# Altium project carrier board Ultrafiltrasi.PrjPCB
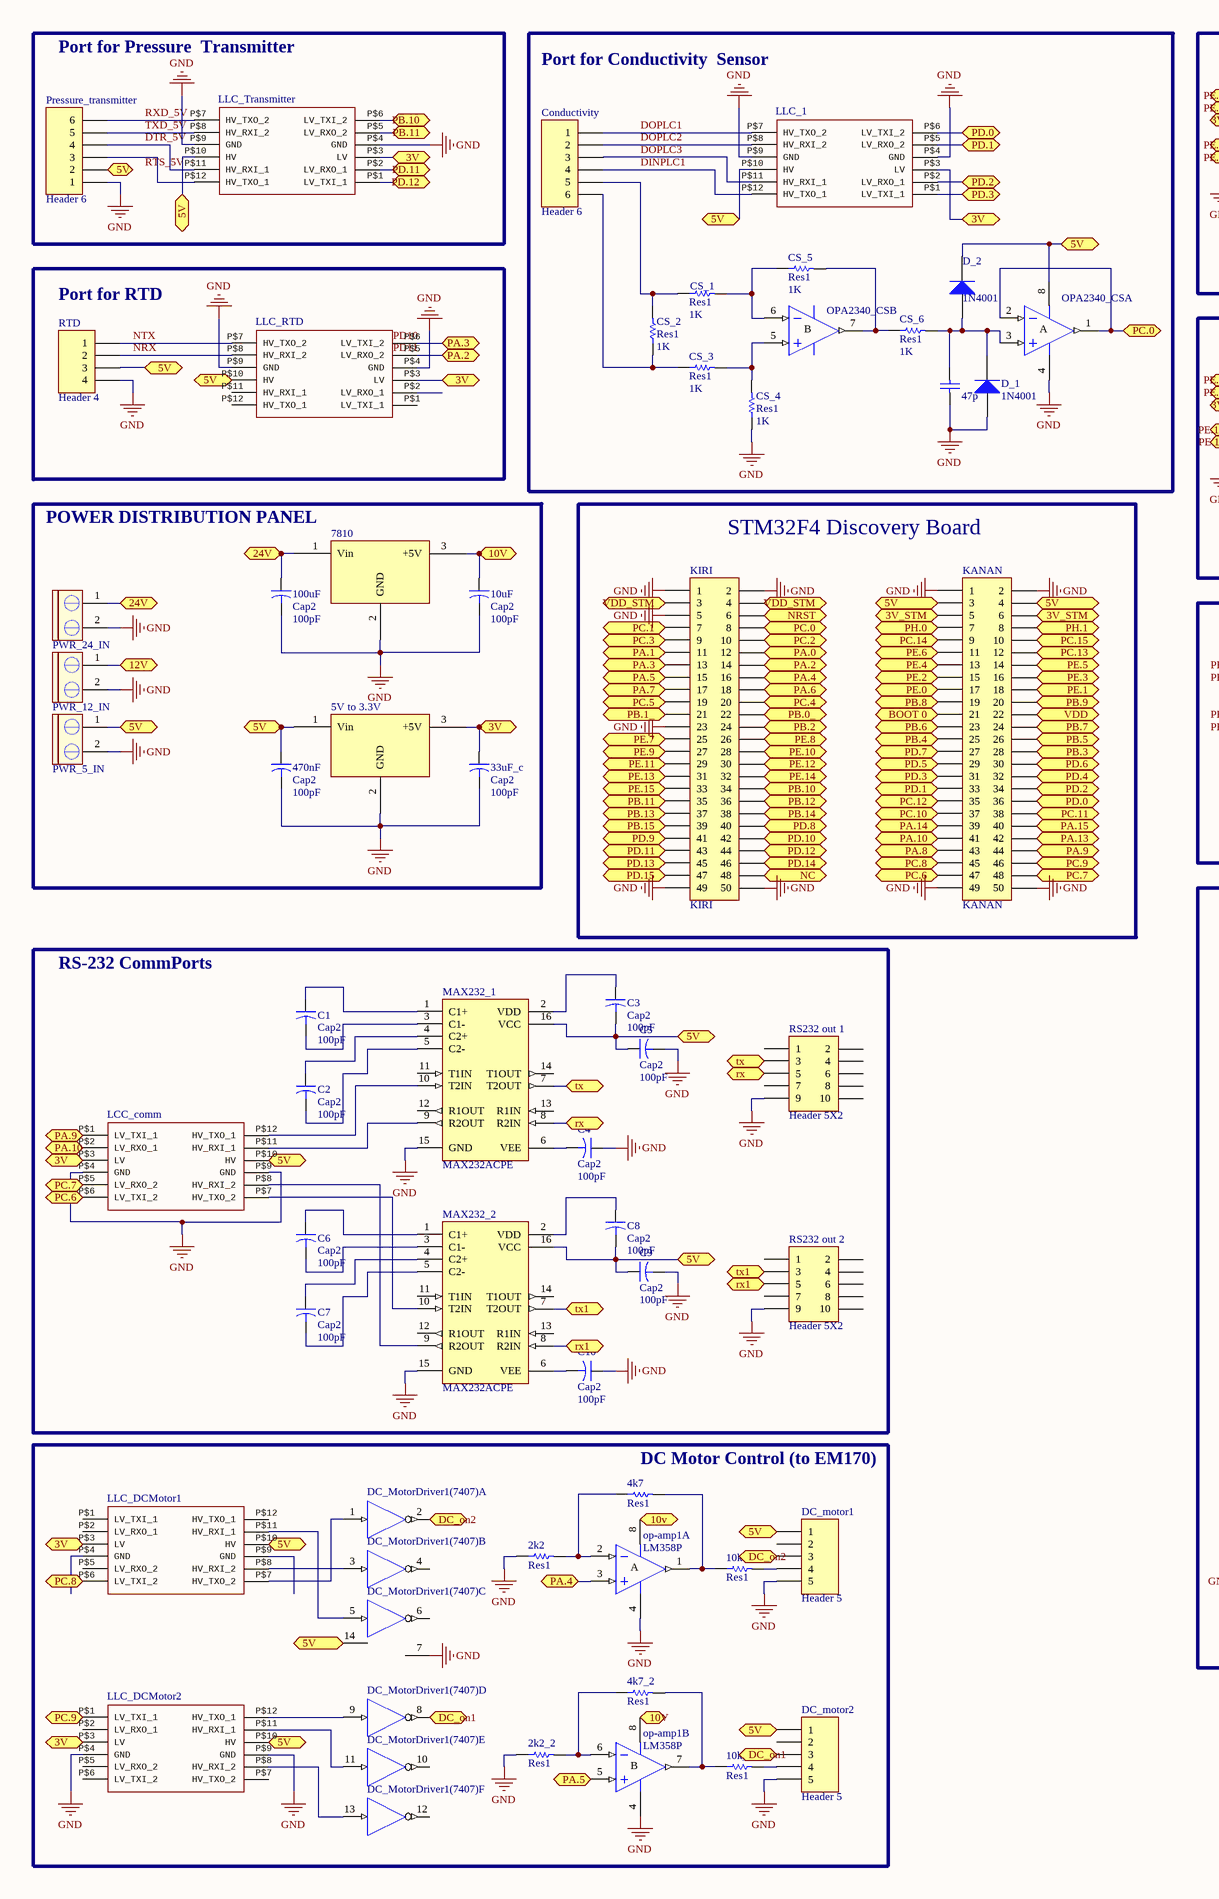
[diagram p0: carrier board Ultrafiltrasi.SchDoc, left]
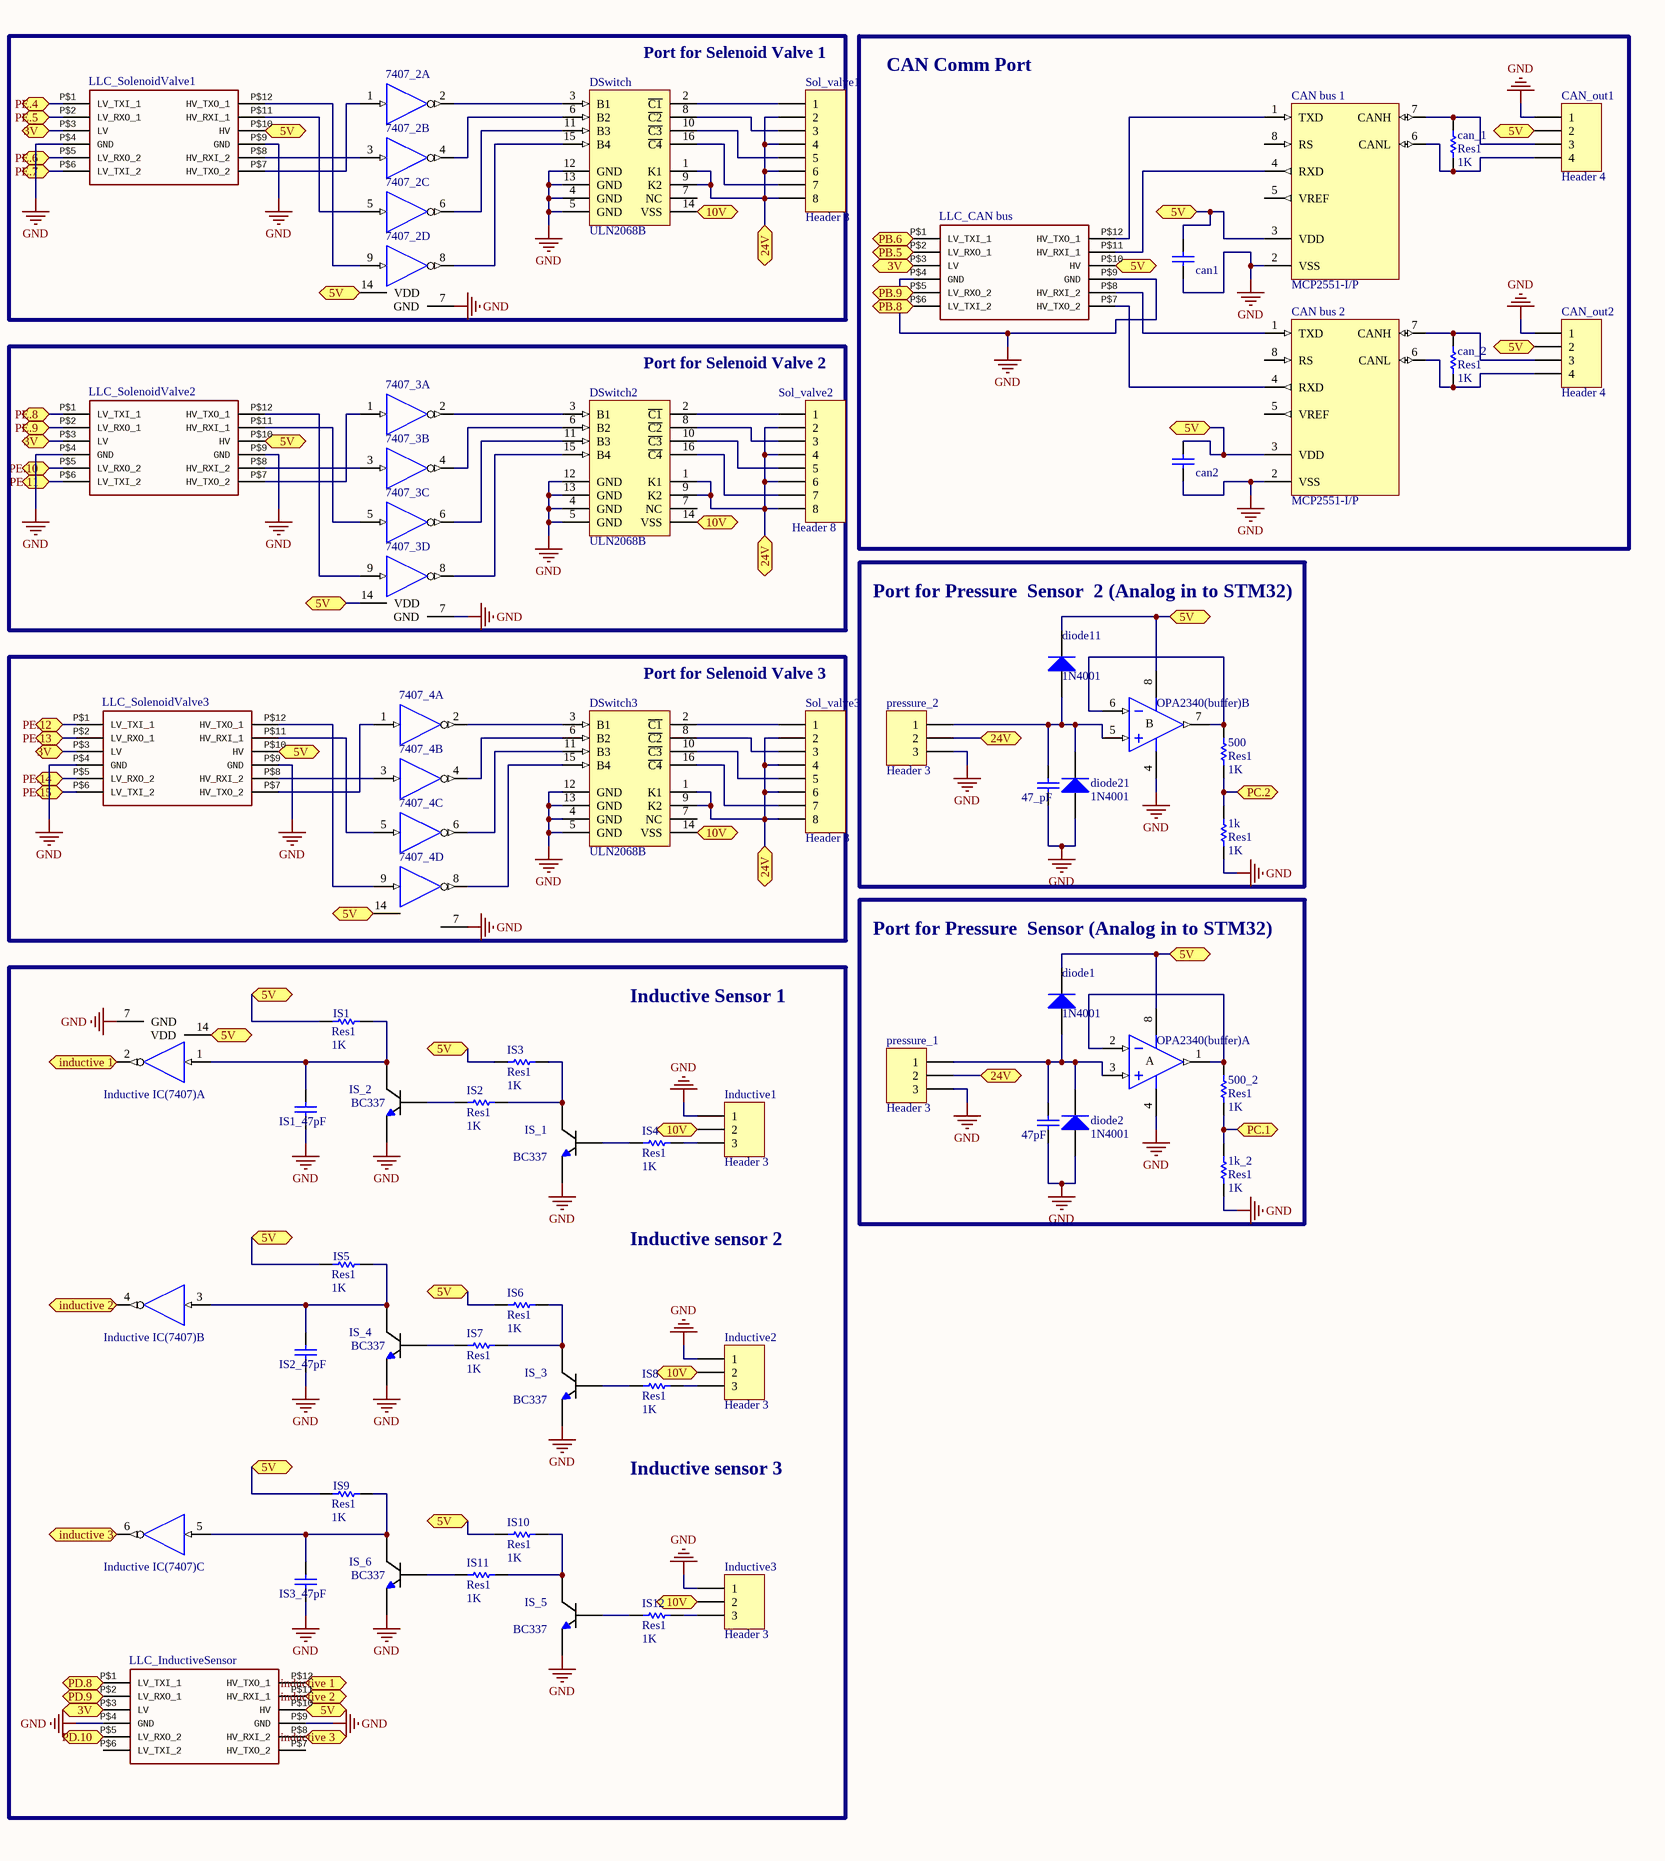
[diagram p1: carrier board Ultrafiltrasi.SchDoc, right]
1 sheet, 114 parts. Net scope: flat (ports and power ports of the same name join across sheets).
Board file: carrier board Ultrafiltrasi.PcbDoc

## Sheet carrier board Ultrafiltrasi.SchDoc: Carrier Board Ultrafiltrasi
size A2

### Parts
1k  Res1  value 1K  [AXIAL-0.3]
1k_2  Res1  value 1K  [AXIAL-0.3]
2k2  Res1  [AXIAL-0.3]
2k2_2  Res1  [AXIAL-0.3]
4k7  Res1  [AXIAL-0.3]
4k7_2  Res1  [AXIAL-0.3]
5V_to_3.3V  7805  [My_TO-220]  (value not drawn)
10k  Res1  [AXIAL-0.3]
10k_2  Res1  [AXIAL-0.3]
10uF  Cap2  value 100pF  [CAPR5-4X5]
33uF_c  Cap2  value 100pF  [CAPR5-4X5]
47_pF  Cap  [My_cap100n]  (value not drawn)
47p  Cap  [My_cap100n]  (value not drawn)
47pF  Cap  [My_cap100n]  (value not drawn)
100uF  Cap2  value 100pF  [CAPR5-4X5]
470nF  Cap2  value 100pF  [CAPR5-4X5]
500  Res1  value 1K  [AXIAL-0.3]
500_2  Res1  value 1K  [AXIAL-0.3]
7407_2  7407  [646-06]  (value not drawn)  (parts A,B,C,D of 6)
7407_3  7407  [646-06]  (value not drawn)  (parts A,B,C,D of 6)
7407_4  7407  [646-06]  (value not drawn)  (parts A,B,C,D of 6)
7810  7805  [My_TO-220]  (value not drawn)
C1  Cap2  value 100pF  [CAPR5-4X5]
C2  Cap2  value 100pF  [CAPR5-4X5]
C3  Cap2  value 100pF  [CAPR5-4X5]
C4  Cap2  value 100pF  [CAPR5-4X5]
C5  Cap2  value 100pF  [CAPR5-4X5]
C6  Cap2  value 100pF  [CAPR5-4X5]
C7  Cap2  value 100pF  [CAPR5-4X5]
C8  Cap2  value 100pF  [CAPR5-4X5]
C9  Cap2  value 100pF  [CAPR5-4X5]
C10  Cap2  value 100pF  [CAPR5-4X5]
can1  Cap  [My_cap100n]  (value not drawn)
can2  Cap  [My_cap100n]  (value not drawn)
can_1  Res1  value 1K  [AXIAL-0.3]
can_2  Res1  value 1K  [AXIAL-0.3]
CAN_bus_1  MCP2551-I/P  [PDIP300-P8]
CAN_bus_2  MCP2551-I/P  [PDIP300-P8]
CAN_out1  Header 4  [HDR1X4]
CAN_out2  Header 4  [HDR1X4]
Conductivity  Header 6  [HDR1X6]
CS_1  Res1  value 1K  [AXIAL-0.3]
CS_2  Res1  value 1K  [AXIAL-0.3]
CS_3  Res1  value 1K  [AXIAL-0.3]
CS_4  Res1  value 1K  [AXIAL-0.3]
CS_5  Res1  value 1K  [AXIAL-0.3]
CS_6  Res1  value 1K  [AXIAL-0.3]
D_1  1N4001  [DO-41]
D_2  1N4001  [DO-41]
DC_motor1  Header 5  [HDR1X5]
DC_motor2  Header 5  [HDR1X5]
DC_MotorDriver1(7407)  SN74LS14N  [646-06]  (value not drawn)  (parts A,B,C,D,E,F of 6)
diode1  1N4001  [DO-41]
diode2  1N4001  [DO-41]
diode11  1N4001  [DO-41]
diode21  1N4001  [DO-41]
DSwitch  ULN2068B  [648C-02]
DSwitch2  ULN2068B  [648C-02]
DSwitch3  ULN2068B  [648C-02]
Inductive1  Header 3  [HDR1X3]
Inductive2  Header 3  [HDR1X3]
Inductive3  Header 3  [HDR1X3]
Inductive_IC(7407)  SN74LS14N  [646-06]  (value not drawn)  (parts A,B,C of 6)
IS1  Res1  value 1K  [AXIAL-0.3]
IS1_47pF  Cap  [My_cap100n]  (value not drawn)
IS2  Res1  value 1K  [AXIAL-0.3]
IS2_47pF  Cap  [My_cap100n]  (value not drawn)
IS3  Res1  value 1K  [AXIAL-0.3]
IS3_47pF  Cap  [My_cap100n]  (value not drawn)
IS4  Res1  value 1K  [AXIAL-0.3]
IS5  Res1  value 1K  [AXIAL-0.3]
IS6  Res1  value 1K  [AXIAL-0.3]
IS7  Res1  value 1K  [AXIAL-0.3]
IS8  Res1  value 1K  [AXIAL-0.3]
IS9  Res1  value 1K  [AXIAL-0.3]
IS10  Res1  value 1K  [AXIAL-0.3]
IS11  Res1  value 1K  [AXIAL-0.3]
IS12  Res1  value 1K  [AXIAL-0.3]
IS_1  BC337  [E3]
IS_2  BC337  [TO-92]
IS_3  BC337  [TO-92]
IS_4  BC337  [transistor]
IS_5  BC337  [TO-92]
IS_6  BC337  [TO-92]
KANAN  KANAN  [HDR2X25]
KIRI  KIRI  [HDR2X25]
LCC_comm  Logic Level Converter (3.3v - 5v) / https://www.sparkfun.com/products/8745  [LOGIC_LEVEL_CONVERTER]  (value not drawn)
LLC_1  Logic Level Converter (3.3v - 5v) / https://www.sparkfun.com/products/8745  [LOGIC_LEVEL_CONVERTER]  (value not drawn)
LLC_CAN_bus  Logic Level Converter (3.3v - 5v) / https://www.sparkfun.com/products/8745  [LOGIC_LEVEL_CONVERTER]  (value not drawn)
LLC_DCMotor1  Logic Level Converter (3.3v - 5v) / https://www.sparkfun.com/products/8745  [LOGIC_LEVEL_CONVERTER]  (value not drawn)
LLC_DCMotor2  Logic Level Converter (3.3v - 5v) / https://www.sparkfun.com/products/8745  [LOGIC_LEVEL_CONVERTER]  (value not drawn)
LLC_InductiveSensor  Logic Level Converter (3.3v - 5v) / https://www.sparkfun.com/products/8745  [LOGIC_LEVEL_CONVERTER]  (value not drawn)
LLC_RTD  Logic Level Converter (3.3v - 5v) / https://www.sparkfun.com/products/8745  [LOGIC_LEVEL_CONVERTER]  (value not drawn)
LLC_SolenoidValve1  Logic Level Converter (3.3v - 5v) / https://www.sparkfun.com/products/8745  [LOGIC_LEVEL_CONVERTER]  (value not drawn)
LLC_SolenoidValve2  Logic Level Converter (3.3v - 5v) / https://www.sparkfun.com/products/8745  [LOGIC_LEVEL_CONVERTER]  (value not drawn)
LLC_SolenoidValve3  Logic Level Converter (3.3v - 5v) / https://www.sparkfun.com/products/8745  [LOGIC_LEVEL_CONVERTER]  (value not drawn)
LLC_Transmitter  Logic Level Converter (3.3v - 5v) / https://www.sparkfun.com/products/8745  [LOGIC_LEVEL_CONVERTER]  (value not drawn)
MAX232_1  MAX232ACPE  [PE16A]
MAX232_2  MAX232ACPE  [PE16A]
op-amp1  LM358P  [P008]  (parts A,B of 2)
OPA2340(buffer)  LM358P  [P008]  (value not drawn)  (parts A,B of 2)
OPA2340_CS  LM358P  [P008]  (value not drawn)  (parts A,B of 2)
pressure_1  Header 3  [HDR1X3]
pressure_2  Header 3  [HDR1X3]
Pressure_transmitter  Header 6  [HDR1X6]
PWR_5_IN  CON2 pin blue  [My_CN2]  (value not drawn)
PWR_12_IN  CON2 pin blue  [My_CN2]  (value not drawn)
PWR_24_IN  CON2 pin blue  [My_CN2]  (value not drawn)
RS232_out_1  Header 5X2  [HDR2X5]
RS232_out_2  Header 5X2  [HDR2X5]
RTD  Header 4  [HDR1X4]
Sol_valve1  Header 8  [HDR1X8]
Sol_valve2  Header 8  [HDR1X8]
Sol_valve3  Header 8  [HDR1X8]

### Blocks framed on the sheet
Port for Pressure  Transmitter: LLC_Transmitter Pressure_transmitter
Port for Conductivity  Sensor: 47p Conductivity CS_1-CS_6 D_1 D_2 LLC_1 OPA2340_CS
Port for Selenoid Valve 1: 7407_2 DSwitch LLC_SolenoidValve1 Sol_valve1
CAN Comm Port: can1 can2 can_1 can_2 CAN_bus_1 CAN_bus_2 CAN_out1 CAN_out2 LLC_CAN_bus
Port for RTD: LLC_RTD RTD
Port for Selenoid Valve 2: 7407_3 DSwitch2 LLC_SolenoidValve2 Sol_valve2
POWER DISTRIBUTION PANEL: 5V_to_3.3V 10uF 33uF_c 100uF 470nF 7810 PWR_5_IN PWR_12_IN PWR_24_IN
STM32F4 Discovery Board: KANAN KIRI
Port for Pressure  Sensor  2 (Analog in to STM32): 1k 47_pF 500 diode11 diode21 OPA2340(buffer) pressure_2
Port for Selenoid Valve 3: 7407_4 DSwitch3 LLC_SolenoidValve3 Sol_valve3
Port for Pressure  Sensor (Analog in to STM32): 1k_2 47pF 500_2 diode1 diode2 OPA2340(buffer) pressure_1
RS-232 CommPorts: C1-C10 LCC_comm MAX232_1 MAX232_2 RS232_out_1 RS232_out_2
DC Motor Control (to EM170): 2k2 2k2_2 4k7 4k7_2 10k 10k_2 DC_motor1 DC_motor2 DC_MotorDriver1(7407) LLC_DCMotor1 LLC_DCMotor2 op-amp1

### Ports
3V, 3V_STM, 5V, 10V, 10v, 12V, 24V, BOOT 0, DC_on1, DC_on2, inductive 1, inductive 2, inductive 3, NC, NRST, PA.0, PA.1, PA.2, PA.3, PA.4, PA.5, PA.6, PA.7, PA.8, PA.9, PA.10, PA.13, PA.14, PA.15, PB.0_, PB.1_, PB.2, PB.3, PB.4, PB.5, PB.6, PB.7, PB.8, PB.9, PB.10, PB.11, PB.12, PB.13, PB.14, PB.15, PC.0, PC.1, PC.2, PC.3, PC.4, PC.5, PC.6, PC.7, PC.8, PC.9, PC.10, PC.11, PC.12, PC.13, PC.14, PC.15, PD.0, PD.1, PD.2, PD.3, PD.4, PD.5, PD.6, PD.7, PD.8, PD.9, PD.10, PD.11, PD.12, PD.13, PD.14, PD.15, PE.0, PE.1, PE.2, PE.3, PE.4, PE.5, PE.6, PE.7, PE.8, PE.9, PE.10, PE.11, PE.12, PE.13, PE.14, PE.15, PH.0, PH.1, rx, rx1, tx, tx1, VDD, VDD_STM

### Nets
GND: 1k.1 1k_2.1 2k2.1 2k2_2.1 5V_to_3.3V.2(GND) 10uF.2 33uF_c.2 47_pF.1 47p.1 47pF.1 100uF.2 470nF.2 7407_2.7(GND) 7407_3.7(GND) 7407_4.7(GND) 7810.2(GND) C4.1 C5.2 C9.2 C10.1 can1.1 can2.1 CAN_bus_1.2(VSS) CAN_bus_2.2(VSS) CAN_out1.1 CAN_out2.1 CS_4.1 D_1.1(A) DC_motor1.5 DC_motor2.5 DC_MotorDriver1(7407).7(GND) diode2.1(A) diode21.1(A) DSwitch.4(GND) DSwitch.5(GND) DSwitch.12(GND) DSwitch.13(GND) DSwitch2.4(GND) DSwitch2.5(GND) DSwitch2.12(GND) DSwitch2.13(GND) DSwitch3.4(GND) DSwitch3.5(GND) DSwitch3.12(GND) DSwitch3.13(GND) Inductive1.1 Inductive2.1 Inductive3.1 Inductive_IC(7407).7(GND) IS1_47pF.1 IS2_47pF.1 IS3_47pF.1 IS_1.3(E) IS_2.3(E) IS_3.3(E) IS_4.3(E) IS_5.3(E) IS_6.3(E) KANAN.1 KANAN.2 KANAN.49 KANAN.50 KIRI.1 KIRI.2 KIRI.5 KIRI.23 KIRI.49 KIRI.50 LCC_comm.P$4(GND) LCC_comm.P$9(GND) LLC_1.P$4(GND) LLC_1.P$9(GND) LLC_CAN_bus.P$4(GND) LLC_CAN_bus.P$9(GND) LLC_DCMotor2.P$4(GND) LLC_DCMotor2.P$9(GND) LLC_InductiveSensor.P$4(GND) LLC_InductiveSensor.P$9(GND) LLC_RTD.P$4(GND) LLC_RTD.P$9(GND) LLC_SolenoidValve1.P$4(GND) LLC_SolenoidValve1.P$9(GND) LLC_SolenoidValve2.P$4(GND) LLC_SolenoidValve2.P$9(GND) LLC_SolenoidValve3.P$4(GND) LLC_SolenoidValve3.P$9(GND) LLC_Transmitter.P$4(GND) LLC_Transmitter.P$9(GND) MAX232_1.15(GND) MAX232_2.15(GND) op-amp1.4(V-) OPA2340(buffer).4(V-) OPA2340_CS.4(V-) pressure_1.3 pressure_2.3 Pressure_transmitter.1 PWR_5_IN.2 PWR_12_IN.2 PWR_24_IN.2 RS232_out_1.9 RS232_out_2.9 RTD.4
VDD: 7407_2.14(VDD) 7407_3.14(VDD) 7407_4.14(VDD) DC_MotorDriver1(7407).14(VDD) Inductive_IC(7407).14(VDD)
DINPLC1: Conductivity.4 LLC_1.P$12(HV_TXO_1)
DOPLC1: Conductivity.1 LLC_1.P$7(HV_TXO_2)
DOPLC2: Conductivity.2 LLC_1.P$8(HV_RXI_2)
DOPLC3: Conductivity.3 LLC_1.P$11(HV_RXI_1)
DTR_5V: LLC_Transmitter.P$11(HV_RXI_1) Pressure_transmitter.4
NRX: LLC_RTD.P$8(HV_RXI_2) RTD.2
NTX: LLC_RTD.P$7(HV_TXO_2) RTD.1
RXD_5V: LLC_Transmitter.P$7(HV_TXO_2) Pressure_transmitter.6
TXD_5V: LLC_Transmitter.P$8(HV_RXI_2) Pressure_transmitter.5
Net1k_2: 1k.2 500.1 KIRI.10 ; port PC.2
Net1k_2_2: 1k_2.2 500_2.1 KIRI.7 ; port PC.1
Net2k2_2: 2k2.2 4k7.1 op-amp1.2(IN-)
Net2k2_2_2: 2k2_2.2 4k7_2.1 op-amp1.6(IN-)
Net4k7_2: 4k7.2 10k.1 op-amp1.1(OUT)
Net4k7_2_2: 4k7_2.2 10k_2.1 op-amp1.7(OUT)
Net5V_to_3.3V_1: 5V_to_3.3V.1(Vin) 470nF.1 7407_2.14(VDD) 7407_3.14(VDD) 7407_4.14(VDD) C3.2 C5.1 C8.2 C9.1 can1.2 can2.2 CAN_bus_1.3(VDD) CAN_bus_2.3(VDD) CAN_out1.2 CAN_out2.2 D_2.2(K) DC_motor1.1 DC_motor2.1 DC_MotorDriver1(7407).14(VDD) diode1.2(K) diode11.2(K) Inductive_IC(7407).14(VDD) IS1.1 IS3.1 IS5.1 IS6.1 IS9.1 IS10.1 KANAN.3 KANAN.4 LCC_comm.P$10(HV) LLC_1.P$10(HV) LLC_CAN_bus.P$10(HV) LLC_DCMotor1.P$10(HV) LLC_DCMotor2.P$10(HV) LLC_InductiveSensor.P$10(HV) LLC_RTD.P$10(HV) LLC_SolenoidValve1.P$10(HV) LLC_SolenoidValve2.P$10(HV) LLC_SolenoidValve3.P$10(HV) LLC_Transmitter.P$10(HV) MAX232_1.16(VCC) MAX232_2.16(VCC) OPA2340(buffer).8(V+) OPA2340_CS.8(V+) Pressure_transmitter.2 PWR_5_IN.1 RTD.3 ; port 5V
Net5V_to_3.3V_3: 5V_to_3.3V.3(+5V) 33uF_c.1 LCC_comm.P$3(LV) LLC_1.P$3(LV) LLC_CAN_bus.P$3(LV) LLC_DCMotor1.P$3(LV) LLC_DCMotor2.P$3(LV) LLC_InductiveSensor.P$3(LV) LLC_RTD.P$3(LV) LLC_SolenoidValve1.P$3(LV) LLC_SolenoidValve2.P$3(LV) LLC_SolenoidValve3.P$3(LV) LLC_Transmitter.P$3(LV) ; port 3V
Net10k_2: 10k.2 DC_motor1.4
Net10k_2_2: 10k_2.2 DC_motor2.4
Net10uF_1: 10uF.1 7810.3(+5V) DSwitch.14(VSS) DSwitch2.14(VSS) DSwitch3.14(VSS) Inductive1.2 Inductive2.2 Inductive3.2 op-amp1.8(V+) ; port 10V, port 10v
Net47_pF_2: 47_pF.2 diode11.1(A) diode21.2(K) OPA2340(buffer).5(IN+) pressure_2.1
Net47p_2: 47p.2 CS_6.2 D_1.2(K) D_2.1(A) OPA2340_CS.3(IN+)
Net47pF_2: 47pF.2 diode1.1(A) diode2.2(K) OPA2340(buffer).3(IN+) pressure_1.1
Net100uF_1: 100uF.1 7810.1(Vin) DSwitch.1(K1) DSwitch.9(K2) DSwitch2.1(K1) DSwitch2.9(K2) DSwitch3.1(K1) DSwitch3.9(K2) pressure_1.2 pressure_2.2 PWR_24_IN.1 Sol_valve1.2 Sol_valve1.4 Sol_valve1.6 Sol_valve1.8 Sol_valve2.2 Sol_valve2.4 Sol_valve2.6 Sol_valve2.8 Sol_valve3.2 Sol_valve3.4 Sol_valve3.6 Sol_valve3.8 ; port 24V
Net500_2: 500.2 OPA2340(buffer).6(IN-) OPA2340(buffer).7(OUT)
Net500_2_2: 500_2.2 OPA2340(buffer).1(OUT) OPA2340(buffer).2(IN-)
Net7407_2_1: 7407_2.1(IN) LLC_SolenoidValve1.P$7(HV_TXO_2)
Net7407_2_2: 7407_2.2(~{OUT}) DSwitch.3(B1)
Net7407_2_3: 7407_2.3(IN) LLC_SolenoidValve1.P$8(HV_RXI_2)
Net7407_2_4: 7407_2.4(~{OUT}) DSwitch.6(B2)
Net7407_2_5: 7407_2.5(IN) LLC_SolenoidValve1.P$11(HV_RXI_1)
Net7407_2_6: 7407_2.6(~{OUT}) DSwitch.11(B3)
Net7407_2_8: 7407_2.8(~{OUT}) DSwitch.15(B4)
Net7407_2_9: 7407_2.9(IN) LLC_SolenoidValve1.P$12(HV_TXO_1)
Net7407_3_1: 7407_3.1(IN) LLC_SolenoidValve2.P$7(HV_TXO_2)
Net7407_3_2: 7407_3.2(~{OUT}) DSwitch2.3(B1)
Net7407_3_3: 7407_3.3(IN) LLC_SolenoidValve2.P$8(HV_RXI_2)
Net7407_3_4: 7407_3.4(~{OUT}) DSwitch2.6(B2)
Net7407_3_5: 7407_3.5(IN) LLC_SolenoidValve2.P$11(HV_RXI_1)
Net7407_3_6: 7407_3.6(~{OUT}) DSwitch2.11(B3)
Net7407_3_8: 7407_3.8(~{OUT}) DSwitch2.15(B4)
Net7407_3_9: 7407_3.9(IN) LLC_SolenoidValve2.P$12(HV_TXO_1)
Net7407_4_1: 7407_4.1(IN) LLC_SolenoidValve3.P$7(HV_TXO_2)
Net7407_4_2: 7407_4.2(~{OUT}) DSwitch3.3(B1)
Net7407_4_3: 7407_4.3(IN) LLC_SolenoidValve3.P$8(HV_RXI_2)
Net7407_4_4: 7407_4.4(~{OUT}) DSwitch3.6(B2)
Net7407_4_5: 7407_4.5(IN) LLC_SolenoidValve3.P$11(HV_RXI_1)
Net7407_4_6: 7407_4.6(~{OUT}) DSwitch3.11(B3)
Net7407_4_8: 7407_4.8(~{OUT}) DSwitch3.15(B4)
Net7407_4_9: 7407_4.9(IN) LLC_SolenoidValve3.P$12(HV_TXO_1)
NetC1_1: C1.1 MAX232_1.1(C1+)
NetC1_2: C1.2 MAX232_1.3(C1-)
NetC2_1: C2.1 MAX232_1.4(C2+)
NetC2_2: C2.2 MAX232_1.5(C2-)
NetC3_1: C3.1 MAX232_1.2(VDD)
NetC4_2: C4.2 MAX232_1.6(VEE)
NetC6_1: C6.1 MAX232_2.1(C1+)
NetC6_2: C6.2 MAX232_2.3(C1-)
NetC7_1: C7.1 MAX232_2.4(C2+)
NetC7_2: C7.2 MAX232_2.5(C2-)
NetC8_1: C8.1 MAX232_2.2(VDD)
NetC10_2: C10.2 MAX232_2.6(VEE)
Netcan_1_1: can_1.1 CAN_bus_1.6(CANL) CAN_out1.4
Netcan_1_2: can_1.2 CAN_bus_1.7(CANH) CAN_out1.3
Netcan_2_1: can_2.1 CAN_bus_2.6(CANL) CAN_out2.4
Netcan_2_2: can_2.2 CAN_bus_2.7(CANH) CAN_out2.3
NetCAN_bus_1_1: CAN_bus_1.1(TXD) LLC_CAN_bus.P$12(HV_TXO_1)
NetCAN_bus_1_4: CAN_bus_1.4(RXD) LLC_CAN_bus.P$11(HV_RXI_1)
NetCAN_bus_2_1: CAN_bus_2.1(TXD) LLC_CAN_bus.P$8(HV_RXI_2)
NetCAN_bus_2_4: CAN_bus_2.4(RXD) LLC_CAN_bus.P$7(HV_TXO_2)
NetConductivity_5: Conductivity.5 CS_1.1 CS_2.2
NetConductivity_6: Conductivity.6 CS_2.1 CS_3.1
NetCS_1_2: CS_1.2 CS_5.1 OPA2340_CS.6(IN-)
NetCS_3_2: CS_3.2 CS_4.2 OPA2340_CS.5(IN+)
NetCS_5_2: CS_5.2 CS_6.1 OPA2340_CS.7(OUT)
NetDC_motor1_3: DC_motor1.3 DC_MotorDriver1(7407).2(~{OUT}) ; port DC_on2
NetDC_motor2_3: DC_motor2.3 DC_MotorDriver1(7407).8(~{OUT}) ; port DC_on1
NetDC_MotorDriver1(7407)_1: DC_MotorDriver1(7407).1(IN) LLC_DCMotor1.P$7(HV_TXO_2)
NetDC_MotorDriver1(7407)_3: DC_MotorDriver1(7407).3(IN) LLC_DCMotor1.P$8(HV_RXI_2)
NetDC_MotorDriver1(7407)_5: DC_MotorDriver1(7407).5(IN) LLC_DCMotor1.P$11(HV_RXI_1)
NetDC_MotorDriver1(7407)_9: DC_MotorDriver1(7407).9(IN) LLC_DCMotor2.P$12(HV_TXO_1)
NetDC_MotorDriver1(7407)_11: DC_MotorDriver1(7407).11(IN) LLC_DCMotor2.P$11(HV_RXI_1)
NetDC_MotorDriver1(7407)_13: DC_MotorDriver1(7407).13(IN) LLC_DCMotor2.P$8(HV_RXI_2)
NetDSwitch2_2: DSwitch2.2(~{C1}) Sol_valve2.1
NetDSwitch2_8: DSwitch2.8(~{C2}) Sol_valve2.3
NetDSwitch2_10: DSwitch2.10(~{C3}) Sol_valve2.5
NetDSwitch2_16: DSwitch2.16(~{C4}) Sol_valve2.7
NetDSwitch3_2: DSwitch3.2(~{C1}) Sol_valve3.1
NetDSwitch3_8: DSwitch3.8(~{C2}) Sol_valve3.3
NetDSwitch3_10: DSwitch3.10(~{C3}) Sol_valve3.5
NetDSwitch3_16: DSwitch3.16(~{C4}) Sol_valve3.7
NetDSwitch_2: DSwitch.2(~{C1}) Sol_valve1.1
NetDSwitch_8: DSwitch.8(~{C2}) Sol_valve1.3
NetDSwitch_10: DSwitch.10(~{C3}) Sol_valve1.5
NetDSwitch_16: DSwitch.16(~{C4}) Sol_valve1.7
NetInductive1_3: Inductive1.3 IS4.2
NetInductive2_3: Inductive2.3 IS8.2
NetInductive3_3: Inductive3.3 IS12.2
NetInductive_IC(7407)_1: Inductive_IC(7407).1(IN) IS1.2 IS1_47pF.2 IS_2.1(C)
NetInductive_IC(7407)_2: Inductive_IC(7407).2(~{OUT}) LLC_InductiveSensor.P$12(HV_TXO_1) ; port inductive 1
NetInductive_IC(7407)_3: Inductive_IC(7407).3(IN) IS2_47pF.2 IS5.2 IS_4.1(C)
NetInductive_IC(7407)_4: Inductive_IC(7407).4(~{OUT}) LLC_InductiveSensor.P$11(HV_RXI_1) ; port inductive 2
NetInductive_IC(7407)_5: Inductive_IC(7407).5(IN) IS3_47pF.2 IS9.2 IS_6.1(C)
NetInductive_IC(7407)_6: Inductive_IC(7407).6(~{OUT}) LLC_InductiveSensor.P$8(HV_RXI_2) ; port inductive 3
NetIS2_1: IS2.1 IS_2.2(B)
NetIS2_2: IS2.2 IS3.2 IS_1.1(C)
NetIS4_1: IS4.1 IS_1.2(B)
NetIS6_2: IS6.2 IS7.2 IS_3.1(C)
NetIS7_1: IS7.1 IS_4.2(B)
NetIS8_1: IS8.1 IS_3.2(B)
NetIS10_2: IS10.2 IS11.2 IS_5.1(C)
NetIS11_1: IS11.1 IS_6.2(B)
NetIS12_1: IS12.1 IS_5.2(B)
NetKANAN_5: KANAN.5 KANAN.6 ; port 3V_STM
NetKANAN_7: KANAN.7 ; port PH.0
NetKANAN_8: KANAN.8 ; port PH.1
NetKANAN_9: KANAN.9 ; port PC.14
NetKANAN_10: KANAN.10 ; port PC.15
NetKANAN_11: KANAN.11 LLC_SolenoidValve1.P$5(LV_RXO_2) ; port PE.6
NetKANAN_12: KANAN.12 ; port PC.13
NetKANAN_13: KANAN.13 LLC_SolenoidValve1.P$1(LV_TXI_1) ; port PE.4
NetKANAN_14: KANAN.14 LLC_SolenoidValve1.P$2(LV_RXO_1) ; port PE.5
NetKANAN_15: KANAN.15 ; port PE.2
NetKANAN_16: KANAN.16 ; port PE.3
NetKANAN_17: KANAN.17 ; port PE.0
NetKANAN_18: KANAN.18 ; port PE.1
NetKANAN_19: KANAN.19 LLC_CAN_bus.P$6(LV_TXI_2) ; port PB.8
NetKANAN_20: KANAN.20 LLC_CAN_bus.P$5(LV_RXO_2) ; port PB.9
NetKANAN_21: KANAN.21 ; port BOOT 0
NetKANAN_22: KANAN.22 ; port VDD
NetKANAN_23: KANAN.23 LLC_CAN_bus.P$1(LV_TXI_1) ; port PB.6
NetKANAN_24: KANAN.24 ; port PB.7
NetKANAN_25: KANAN.25 ; port PB.4
NetKANAN_26: KANAN.26 LLC_CAN_bus.P$2(LV_RXO_1) ; port PB.5
NetKANAN_27: KANAN.27 ; port PD.7
NetKANAN_28: KANAN.28 ; port PB.3
NetKANAN_29: KANAN.29 ; port PD.5
NetKANAN_30: KANAN.30 ; port PD.6
NetKANAN_31: KANAN.31 LLC_1.P$1(LV_TXI_1) ; port PD.3
NetKANAN_32: KANAN.32 ; port PD.4
NetKANAN_33: KANAN.33 LLC_1.P$5(LV_RXO_2) ; port PD.1
NetKANAN_34: KANAN.34 LLC_1.P$2(LV_RXO_1) ; port PD.2
NetKANAN_35: KANAN.35 ; port PC.12
NetKANAN_36: KANAN.36 LLC_1.P$6(LV_TXI_2) ; port PD.0
NetKANAN_37: KANAN.37 ; port PC.10
NetKANAN_38: KANAN.38 ; port PC.11
NetKANAN_39: KANAN.39 ; port PA.14
NetKANAN_40: KANAN.40 ; port PA.15
NetKANAN_41: KANAN.41 LCC_comm.P$2(LV_RXO_1) ; port PA.10
NetKANAN_42: KANAN.42 ; port PA.13
NetKANAN_43: KANAN.43 ; port PA.8
NetKANAN_44: KANAN.44 LCC_comm.P$1(LV_TXI_1) ; port PA.9
NetKANAN_45: KANAN.45 LLC_DCMotor1.P$6(LV_TXI_2) ; port PC.8
NetKANAN_46: KANAN.46 LLC_DCMotor2.P$1(LV_TXI_1) ; port PC.9
NetKANAN_47: KANAN.47 LCC_comm.P$6(LV_TXI_2) ; port PC.6
NetKANAN_48: KANAN.48 LCC_comm.P$5(LV_RXO_2) ; port PC.7
NetKIRI_3: KIRI.3 KIRI.4 ; port VDD_STM
NetKIRI_6: KIRI.6 ; port NRST
NetKIRI_8: KIRI.8 OPA2340_CS.1(OUT) OPA2340_CS.2(IN-) ; port PC.0
NetKIRI_9: KIRI.9 ; port PC.3
NetKIRI_11: KIRI.11 ; port PA.1
NetKIRI_12: KIRI.12 ; port PA.0
NetKIRI_13: KIRI.13 LLC_RTD.P$6(LV_TXI_2) ; port PA.3
NetKIRI_14: KIRI.14 LLC_RTD.P$5(LV_RXO_2) ; port PA.2
NetKIRI_15: KIRI.15 op-amp1.5(IN+) ; port PA.5
NetKIRI_16: KIRI.16 op-amp1.3(IN+) ; port PA.4
NetKIRI_17: KIRI.17 ; port PA.7
NetKIRI_18: KIRI.18 ; port PA.6
NetKIRI_19: KIRI.19 ; port PC.5
NetKIRI_20: KIRI.20 ; port PC.4
NetKIRI_21: KIRI.21 ; port PB.1_
NetKIRI_22: KIRI.22 ; port PB.0_
NetKIRI_24: KIRI.24 ; port PB.2
NetKIRI_25: KIRI.25 LLC_SolenoidValve1.P$6(LV_TXI_2) ; port PE.7
NetKIRI_26: KIRI.26 LLC_SolenoidValve2.P$1(LV_TXI_1) ; port PE.8
NetKIRI_27: KIRI.27 LLC_SolenoidValve2.P$2(LV_RXO_1) ; port PE.9
NetKIRI_28: KIRI.28 LLC_SolenoidValve2.P$5(LV_RXO_2) ; port PE.10
NetKIRI_29: KIRI.29 LLC_SolenoidValve2.P$6(LV_TXI_2) ; port PE.11
NetKIRI_30: KIRI.30 LLC_SolenoidValve3.P$1(LV_TXI_1) ; port PE.12
NetKIRI_31: KIRI.31 LLC_SolenoidValve3.P$2(LV_RXO_1) ; port PE.13
NetKIRI_32: KIRI.32 LLC_SolenoidValve3.P$5(LV_RXO_2) ; port PE.14
NetKIRI_33: KIRI.33 LLC_SolenoidValve3.P$6(LV_TXI_2) ; port PE.15
NetKIRI_34: KIRI.34 LLC_Transmitter.P$6(LV_TXI_2) ; port PB.10
NetKIRI_35: KIRI.35 LLC_Transmitter.P$5(LV_RXO_2) ; port PB.11
NetKIRI_36: KIRI.36 ; port PB.12
NetKIRI_37: KIRI.37 ; port PB.13
NetKIRI_38: KIRI.38 ; port PB.14
NetKIRI_39: KIRI.39 ; port PB.15
NetKIRI_40: KIRI.40 LLC_InductiveSensor.P$1(LV_TXI_1) ; port PD.8
NetKIRI_41: KIRI.41 LLC_InductiveSensor.P$2(LV_RXO_1) ; port PD.9
NetKIRI_42: KIRI.42 LLC_InductiveSensor.P$5(LV_RXO_2) ; port PD.10
NetKIRI_43: KIRI.43 LLC_Transmitter.P$2(LV_RXO_1) ; port PD.11
NetKIRI_44: KIRI.44 LLC_Transmitter.P$1(LV_TXI_1) ; port PD.12
NetKIRI_45: KIRI.45 ; port PD.13
NetKIRI_46: KIRI.46 ; port PD.14
NetKIRI_47: KIRI.47 ; port PD.15
NetKIRI_48: KIRI.48 ; port NC
NetLCC_comm_P$7: LCC_comm.P$7(HV_TXO_2) MAX232_2.10(T2IN)
NetLCC_comm_P$8: LCC_comm.P$8(HV_RXI_2) MAX232_2.9(R2OUT)
NetLCC_comm_P$11: LCC_comm.P$11(HV_RXI_1) MAX232_1.9(R2OUT)
NetLCC_comm_P$12: LCC_comm.P$12(HV_TXO_1) MAX232_1.10(T2IN)
NetLLC_Transmitter_P$12: LLC_Transmitter.P$12(HV_TXO_1) Pressure_transmitter.3
NetMAX232_1_7: MAX232_1.7(T2OUT) RS232_out_1.3 ; port tx
NetMAX232_1_8: MAX232_1.8(R2IN) RS232_out_1.5 ; port rx
NetMAX232_2_7: MAX232_2.7(T2OUT) RS232_out_2.3 ; port tx1
NetMAX232_2_8: MAX232_2.8(R2IN) RS232_out_2.5 ; port rx1
NetPWR_12_IN_1: PWR_12_IN.1 ; port 12V

Not connected (* = marked no-connect by the designer): CAN_bus_1 5(VREF) 8(RS); CAN_bus_2 5(VREF) 8(RS); DC_motor1 2; DC_motor2 2; DC_MotorDriver1(7407) 4(~{OUT}) 6(~{OUT}) 10(~{OUT}) 12(~{OUT}); DSwitch 7(NC); DSwitch2 7(NC); DSwitch3 7(NC); LLC_DCMotor1 P$1(LV_TXI_1) P$2(LV_RXO_1) P$4(GND) P$5(LV_RXO_2) P$9(GND) P$12(HV_TXO_1); LLC_DCMotor2 P$2(LV_RXO_1) P$5(LV_RXO_2) P$6(LV_TXI_2) P$7(HV_TXO_2); LLC_InductiveSensor P$6(LV_TXI_2) P$7(HV_TXO_2); LLC_RTD P$1(LV_TXI_1) P$2(LV_RXO_1) P$11(HV_RXI_1) P$12(HV_TXO_1); MAX232_1 11(T1IN) 12(R1OUT) 13(R1IN) 14(T1OUT); MAX232_2 11(T1IN) 12(R1OUT) 13(R1IN) 14(T1OUT); RS232_out_1 1 2 4 6 7 8 10; RS232_out_2 1 2 4 6 7 8 10

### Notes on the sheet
- Inductive Sensor 1
- Inductive sensor 2
- Inductive sensor 3
- Labels drawn without touching a wire or pin: PD10, PD11, RTS_5V

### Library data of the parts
1k 1k_2 500 500_2 can_1 can_2 CS_1-CS_6 IS1-IS12 = Res1: Resistor
2k2 2k2_2 4k7 4k7_2 10k_2 = Res1: Resistor; Value: 1K
5V_to_3.3V 7810 = 7805: Regulator
10k = Res1: Resistor; Value: 10k
10uF 33uF_c 100uF 470nF C1-C10 = Cap2: Capacitor
47_pF 47p 47pF can1 can2 IS1_47pF IS2_47pF IS3_47pF = Cap ceramic: CAP-100Nf; Value: 100nF
7407_2-7407_4 DC_MotorDriver1(7407) Inductive_IC(7407) = SN74LS14N: Hex Schmitt-Trigger Inverter
CAN_bus_1 CAN_bus_2 = MCP2551-I/P: High-Speed CAN Transceiver, 8-Pin PDIP, Industrial Temperature
CAN_out1 CAN_out2 RTD = Header 4: Header, 4-Pin
Conductivity Pressure_transmitter = Header 6: Header, 6-Pin
D_1 D_2 diode1 diode2 diode11 diode21 = Diode 1N4001: 1 Amp General Purpose Rectifier
DC_motor1 DC_motor2 = Header 5: Header, 5-Pin
DSwitch DSwitch2 DSwitch3 = ULN2068B: Quad 1.5A Darlington Switch
Inductive1-Inductive3 pressure_1 pressure_2 = Header 3: Header, 3-Pin
IS_1-IS_6 = BC337: Transistor, NPN, 300MHz, 40V, 200mA, SOT-23 pkg
KANAN KIRI = Header 25X2: Header, 25-Pin, Dual row
LCC_comm LLC_1 LLC_CAN_bus LLC_DCMotor1 LLC_DCMotor2 LLC_InductiveSensor LLC_RTD LLC_SolenoidValve1-LLC_SolenoidValve3 LLC_Transmitter = LOGIC_LEVEL_CONVERTER
MAX232_1 MAX232_2 = MAX232ACPE: +5V Powered, Multi-Channel RS-232 Driver/Receiver
op-amp1 OPA2340(buffer) OPA2340_CS = LM358P: Dual Operational Amplifier
PWR_5_IN PWR_12_IN PWR_24_IN = CON2 pin blue: Connector blue screw
RS232_out_1 RS232_out_2 = Header 5X2: Header, 5-Pin, Dual row
Sol_valve1-Sol_valve3 = Header 8: Header, 8-Pin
